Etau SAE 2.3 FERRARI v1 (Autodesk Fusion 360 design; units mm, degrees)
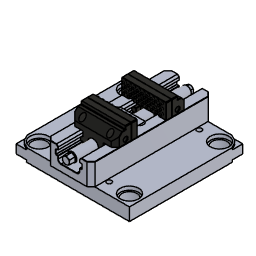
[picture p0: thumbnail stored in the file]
parameter "Ouverture" = 50
base_feature "Base Feature1"
joint_origin "JointOrigin1" OffsetX 0 OffsetY 0 OffsetZ 0
base_feature "Base Feature1"
base_feature "Base Feature1"
base_feature "Base Feature1"
joint_origin "JointOrigin1" OffsetX 0 OffsetY 0 OffsetZ 0
base_feature "Base Feature1"
base_feature "Base Feature1"
base_feature "Base Feature1"
base_feature "Base Feature1"
base_feature "Base Feature1"
base_feature "Base Feature1"
as_built_joint "As-built1"
ground "Ground1"
as_built_joint "As-built1"
as_built_joint "As-built1"
as_built_joint "As-built2"
joint "Assemble1" alignOffsetX 0 alignOffsetY 0 alignOffsetZ 25 (= "Ouverture / 2")
joint "Assemble2" alignOffsetX 0 alignOffsetY 0 alignOffsetZ 25 (= "Ouverture / 2")
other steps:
create_component "CreateComponent1"
create_component "CreateComponent1"
create_component "CreateComponent2"
create_component "CreateComponent2"
create_component "CreateComponent1"
create_component "CreateComponent2"
create_component "CreateComponent3"
create_component "CreateComponent1"
create_component "CreateComponent2"
create_component "CreateComponent3"
create_component "CreateComponent4"
joint_origin "JointOrigin1" OffsetX 0 OffsetY 0 OffsetZ 0
joint_origin "JointOrigin2" OffsetX 0 OffsetY 0 OffsetZ 0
